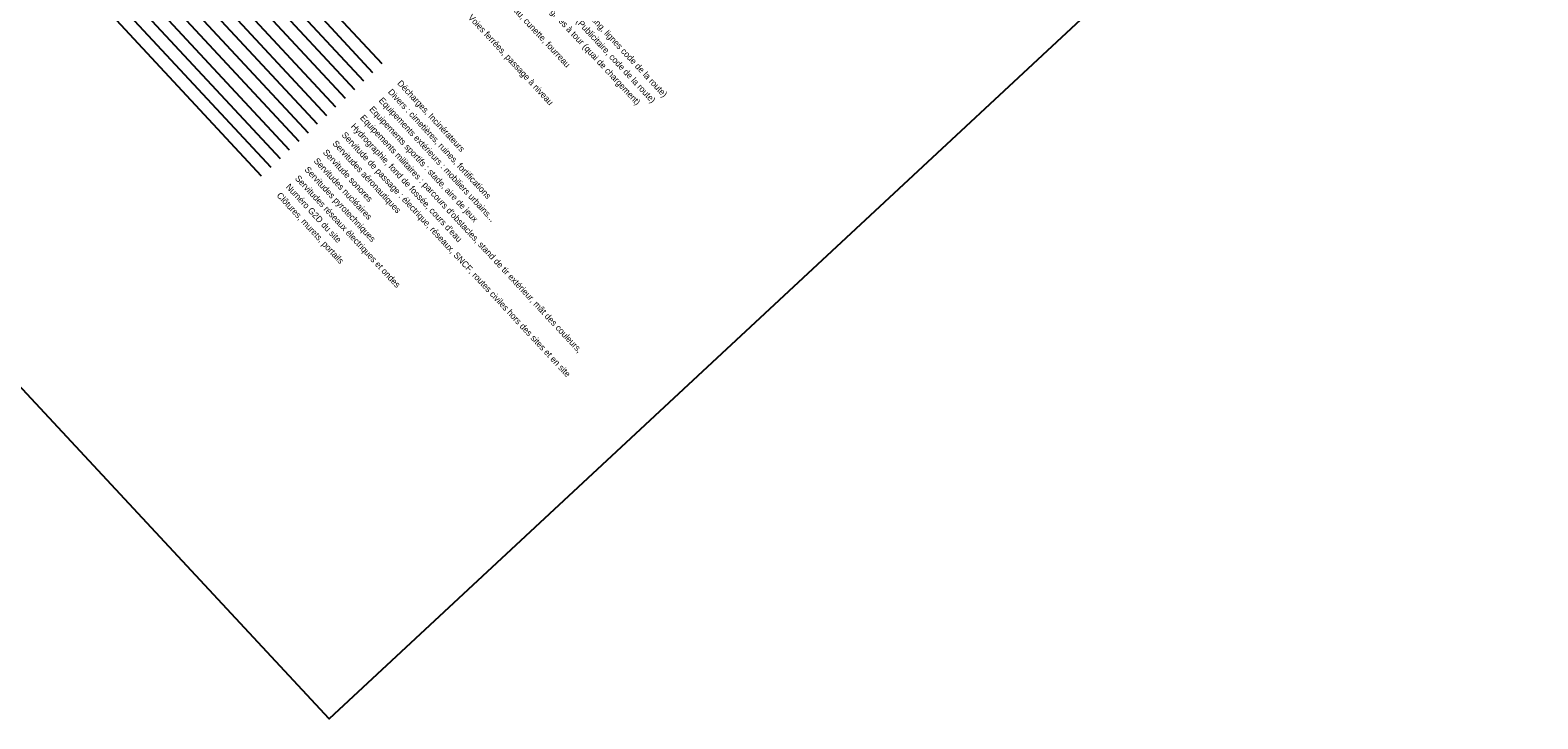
# Model space of a CAD drawing. Extents: x 704383 to 706615, y 7057567 to 7059313.
# Drawn here: x 706378.5 to 706498.3, y 7057566.8 to 7057621.5 of the extents above; entities that cross this region are included whole.
import ezdxf

# ---------------------------------------------------------------- set-up
doc = ezdxf.new("R2010")
doc.units = 0
for name, color, linetype in [('DH_CADRE -CARTOUCHE', 7, 'Continuous'), ('SITE _DIVERS', 7, 'Continuous'), ('SITE _EQUIP EXTERIEUR', 7, 'Continuous'), ('SITE _EQUIP MILITAIRE', 7, 'Continuous'), ('SITE _EQUIP_SPORTIF', 7, 'Continuous'), ('SITE _HYDROGRAPHIE', 7, 'Continuous'), ('SITE _LIMITE_PHYSIQUE', 7, 'Continuous'), ('SITE _SERVITUDE', 7, 'Continuous'), ('SITE _SERVITUDE AERO', 7, 'Continuous'), ('SITE _SERVITUDE BRUIT', 7, 'Continuous'), ('SITE _SERVITUDE NUCL', 7, 'Continuous'), ('SITE _SERVITUDE PYRO', 7, 'Continuous'), ('SITE _SERVITUDE RADIO ELEC', 7, 'Continuous'), ('SITE_CODE_G2D', 7, 'Continuous'), ('SITE_DECHARGE', 7, 'Continuous'), ('VOIRIE_CANIVEAU_TECHNIQUE', 7, 'Continuous'), ('VOIRIE_SIGNAL HORIZON', 7, 'Continuous'), ('VOIRIE_SIGNAL VERTIC', 7, 'Continuous'), ('VOIRIE_VOIES FERREES', 7, 'Continuous'), ('VOIRIE_VOIES GRUE', 7, 'Continuous')]:
    doc.layers.add(name, color=color, linetype=linetype)

msp = doc.modelspace()

# ---------------------------------------------------------------- linework, layer by layer
at = {"layer": 'DH_CADRE -CARTOUCHE'}
msp.add_lwpolyline([(706481.84, 7057811.55), (706566.98, 7057720.03), (706402.25, 7057566.77), (706317.1, 7057658.29)], close=True, dxfattribs=at)
at = {"layer": 'SITE _DIVERS'}
msp.add_line((706388.81, 7057636.32), (706405.71, 7057618.15), dxfattribs=at)
at = {"layer": 'SITE _EQUIP EXTERIEUR'}
msp.add_line((706388.08, 7057635.64), (706404.98, 7057617.47), dxfattribs=at)
at = {"layer": 'SITE _EQUIP MILITAIRE'}
msp.add_line((706386.61, 7057634.28), (706403.53, 7057616.1), dxfattribs=at)
at = {"layer": 'SITE _EQUIP_SPORTIF'}
msp.add_line((706387.35, 7057634.96), (706404.26, 7057616.78), dxfattribs=at)
at = {"layer": 'SITE _HYDROGRAPHIE'}
msp.add_line((706385.86, 7057633.58), (706402.76, 7057615.41), dxfattribs=at)
at = {"layer": 'SITE _LIMITE_PHYSIQUE'}
msp.add_line((706379.96, 7057628.09), (706396.86, 7057609.92), dxfattribs=at)
at = {"layer": 'SITE _SERVITUDE'}
msp.add_line((706385.13, 7057632.9), (706402.03, 7057614.73), dxfattribs=at)
at = {"layer": 'SITE _SERVITUDE AERO'}
msp.add_line((706384.4, 7057632.21), (706401.3, 7057614.05), dxfattribs=at)
at = {"layer": 'SITE _SERVITUDE BRUIT'}
msp.add_line((706383.66, 7057631.53), (706400.58, 7057613.35), dxfattribs=at)
at = {"layer": 'SITE _SERVITUDE NUCL'}
msp.add_line((706382.93, 7057630.85), (706399.84, 7057612.67), dxfattribs=at)
at = {"layer": 'SITE _SERVITUDE PYRO'}
msp.add_line((706382.18, 7057630.15), (706399.08, 7057611.98), dxfattribs=at)
at = {"layer": 'SITE _SERVITUDE RADIO ELEC'}
msp.add_line((706381.44, 7057629.47), (706398.36, 7057611.29), dxfattribs=at)
at = {"layer": 'SITE_CODE_G2D'}
msp.add_line((706380.71, 7057628.79), (706397.62, 7057610.61), dxfattribs=at)
at = {"layer": 'SITE_DECHARGE'}
msp.add_line((706389.54, 7057637), (706406.45, 7057618.84), dxfattribs=at)

# ---------------------------------------------------------------- texts
at = {"layer": 'SITE _DIVERS'}
msp.add_text('Divers : cimetières, ruines, fortifications', height=0.5, rotation=312.9332, dxfattribs=at).set_placement((706406.89, 7057616.56))
at = {"layer": 'SITE _EQUIP EXTERIEUR'}
msp.add_text('Equipements extérieurs : mobiliers urbains...', height=0.5, rotation=312.9332, dxfattribs=at).set_placement((706406.16, 7057615.88))
at = {"layer": 'SITE _EQUIP MILITAIRE'}
msp.add_text("Equipements militaires : parcours d'obstacles, stand de tir extérieur, mât des couleurs,", height=0.5, rotation=312.9332, dxfattribs=at).set_placement((706404.67, 7057614.5))
at = {"layer": 'SITE _EQUIP_SPORTIF'}
msp.add_text('Equipements sportifs : stade, aire de jeux', height=0.5, rotation=312.9332, dxfattribs=at).set_placement((706405.41, 7057615.18))
at = {"layer": 'SITE _HYDROGRAPHIE'}
msp.add_text("Hydrographie, fond de fossée, cours d'eau", height=0.5, rotation=312.9332, dxfattribs=at).set_placement((706403.94, 7057613.82))
at = {"layer": 'SITE _LIMITE_PHYSIQUE'}
msp.add_text('Clôtures, murets, portails', height=0.5, rotation=312.9332, dxfattribs=at).set_placement((706398.04, 7057608.33))
at = {"layer": 'SITE _SERVITUDE'}
msp.add_text('Servitude de passage : électrique, réseaux, SNCF, routes civiles hors des sites et en site', height=0.5, rotation=312.9332, dxfattribs=at).set_placement((706403.21, 7057613.14))
at = {"layer": 'SITE _SERVITUDE AERO'}
msp.add_text('Servitudes aéronautiques', height=0.5, rotation=312.9332, dxfattribs=at).set_placement((706402.48, 7057612.46))
at = {"layer": 'SITE _SERVITUDE BRUIT'}
msp.add_text('Servitude sonores', height=0.5, rotation=312.9332, dxfattribs=at).set_placement((706401.72, 7057611.75))
at = {"layer": 'SITE _SERVITUDE NUCL'}
msp.add_text('Servitudes nucléaires', height=0.5, rotation=312.9332, dxfattribs=at).set_placement((706400.99, 7057611.07))
at = {"layer": 'SITE _SERVITUDE PYRO'}
msp.add_text('Servitudes pyrotechniques', height=0.5, rotation=312.9332, dxfattribs=at).set_placement((706400.26, 7057610.39))
at = {"layer": 'SITE _SERVITUDE RADIO ELEC'}
msp.add_text('Servitudes réseaux électriques et ondes', height=0.5, rotation=312.9332, dxfattribs=at).set_placement((706399.5, 7057609.69))
at = {"layer": 'SITE_CODE_G2D'}
msp.add_text('Numéro G2D du site', height=0.5, rotation=312.9332, dxfattribs=at).set_placement((706398.77, 7057609.01))
at = {"layer": 'SITE_DECHARGE'}
msp.add_text('Décharges, Incinérateurs', height=0.5, rotation=312.9332, dxfattribs=at).set_placement((706407.63, 7057617.25))
at = {"layer": 'VOIRIE_CANIVEAU_TECHNIQUE'}
msp.add_text('Caniveau, cunette, fourreau', height=0.5, rotation=312.9332, dxfattribs=at).set_placement((706415.49, 7057624.53))
at = {"layer": 'VOIRIE_SIGNAL HORIZON'}
msp.add_text('Marquage au sol (parcking, lignes code de la route)', height=0.5, rotation=312.9332, dxfattribs=at).set_placement((706418.44, 7057627.28))
at = {"layer": 'VOIRIE_SIGNAL VERTIC'}
msp.add_text('Panneaux verticaux (Publicitaire, code de la route)', height=0.5, rotation=312.9332, dxfattribs=at).set_placement((706417.71, 7057626.6))
at = {"layer": 'VOIRIE_VOIES FERREES'}
msp.add_text('Voies ferrées, passage à niveau', height=0.5, rotation=312.9332, dxfattribs=at).set_placement((706413.26, 7057622.48))
at = {"layer": 'VOIRIE_VOIES GRUE'}
msp.add_text('Voies ferrées grues à tour (quai de chargement)', height=0.5, rotation=312.9332, dxfattribs=at).set_placement((706416.98, 7057625.92))

doc.saveas('drawing.dxf')
